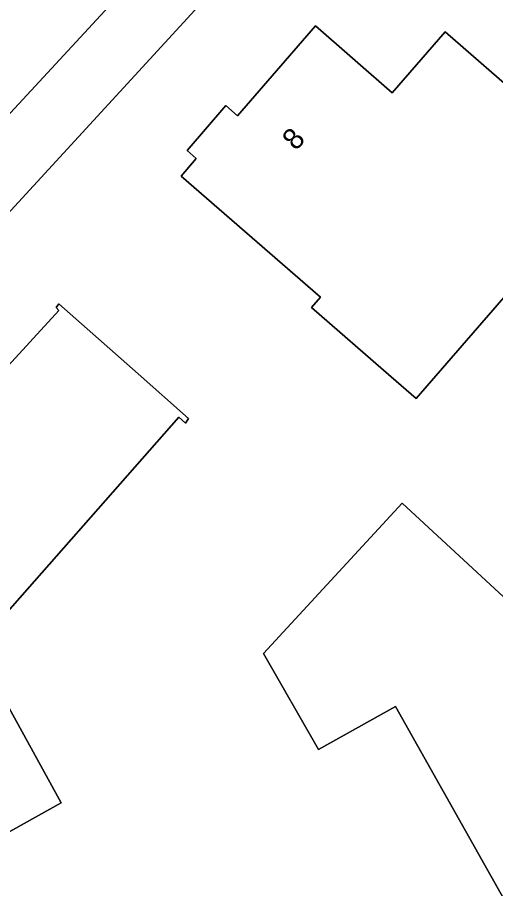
# Model space of a CAD drawing. Extents: x 160023 to 161302, y 384750 to 385707.
# Drawn here: x 160547.86 to 160570.51, y 385276.49 to 385317.72 of the extents above; entities that cross this region are included whole.
import ezdxf

# ---------------------------------------------------------------- set-up
doc = ezdxf.new("R2010")
doc.units = 0
for name, color, linetype in [('IMGEO_Erf', 7, 'Continuous'), ('IMGEO_Pand', 7, 'Continuous'), ('IMGEO_Pand_nummerreeks', 7, 'Continuous'), ('IMGEO_Rijbaan_lokaal_open', 7, 'Continuous'), ('IMGEO_Voetpad_open', 7, 'Continuous')]:
    doc.layers.add(name, color=color, linetype=linetype)

msp = doc.modelspace()

# ---------------------------------------------------------------- linework, layer by layer
at = {"layer": 'IMGEO_Erf'}
msp.add_lwpolyline([(160574.043, 385337.42), (160530.106, 385289.633), (160548.644, 385257.254), (160549.531, 385257.908), (160555.291, 385261.732), (160553.213, 385265.368), (160550.807, 385263.771), (160546.893, 385270.637), (160549.849, 385272.493), (160549.704, 385272.761), (160550.78, 385273.373), (160550.914, 385273.139), (160555.294, 385275.553), (160555.932, 385275.904), (160559.029, 385270.29), (160562.892, 385272.317), (160564.94, 385269.231), (160560.974, 385265.499), (160564.337, 385260.433), (160563.562, 385259.919), (160566.095, 385256.103), (160560.202, 385252.19), (160558.995, 385251.389), (160560.062, 385249.782)], dxfattribs=at)
for points in [[(160574.27, 385301.957), (160571.104, 385304.708), (160566.745, 385299.691), (160565.566, 385300.716), (160561.791, 385303.995), (160562.209, 385304.476), (160555.608, 385310.212), (160556.331, 385311.045), (160555.893, 385311.425), (160557.734, 385313.544), (160558.282, 385313.068), (160561.971, 385317.313), (160565.616, 385314.146), (160568.122, 385317.03), (160571.897, 385313.751), (160579.015, 385307.566), (160581.581, 385310.519), (160579.316, 385312.486), (160581.698, 385315.228), (160586.085, 385311.418), (160583.703, 385308.676), (160587.666, 385305.233), (160584.69, 385301.807), (160578.624, 385307.076)], [(160545.875, 385287.891), (160546.647, 385286.494), (160549.935, 385280.544), (160547.638, 385279.274), (160543.261, 385276.855), (160538.06, 385286.264), (160540.539, 385289.048), (160538.078, 385291.24), (160538.242, 385291.512), (160538.536, 385291.335), (160542.207, 385295.461), (160541.895, 385295.738), (160544.204, 385298.309), (160544.488, 385298.045), (160549.819, 385303.853), (160549.684, 385303.992), (160549.819, 385304.157), (160553.57, 385300.851), (160555.96, 385298.744), (160555.824, 385298.519), (160555.505, 385298.795)], [(160571.341, 385275.212), (160565.771, 385285.111), (160562.121, 385283.08), (160559.517, 385287.619), (160566.089, 385294.733), (160579.218, 385282.604)]]:
    msp.add_lwpolyline(points, close=True, dxfattribs=at)
at = {"layer": 'IMGEO_Pand'}
for points in [[(160579.015, 385307.566), (160571.897, 385313.751), (160568.122, 385317.03), (160565.616, 385314.146), (160561.971, 385317.313), (160558.282, 385313.068), (160557.734, 385313.544), (160555.893, 385311.425), (160556.331, 385311.045), (160555.608, 385310.212), (160562.209, 385304.476), (160561.791, 385303.995), (160565.566, 385300.716), (160566.745, 385299.691), (160571.104, 385304.708), (160574.27, 385301.957), (160578.624, 385307.076), (160584.69, 385301.807), (160587.666, 385305.233), (160583.703, 385308.676), (160586.085, 385311.418), (160581.698, 385315.228), (160579.316, 385312.486), (160581.581, 385310.519)], [(160555.505, 385298.795), (160555.824, 385298.519), (160555.96, 385298.744), (160553.57, 385300.851), (160549.819, 385304.157), (160549.684, 385303.992), (160549.819, 385303.853), (160544.488, 385298.045), (160544.204, 385298.309), (160541.895, 385295.738), (160542.207, 385295.461), (160538.536, 385291.335), (160538.242, 385291.512), (160538.078, 385291.24), (160540.539, 385289.048), (160538.06, 385286.264), (160543.261, 385276.855), (160547.638, 385279.274), (160549.935, 385280.544), (160546.647, 385286.494), (160545.875, 385287.891)], [(160579.218, 385282.604), (160566.089, 385294.733), (160559.517, 385287.619), (160562.121, 385283.08), (160565.771, 385285.111), (160571.341, 385275.212)]]:
    msp.add_lwpolyline(points, close=True, dxfattribs=at)
at = {"layer": 'IMGEO_Rijbaan_lokaal_open'}
msp.add_lwpolyline([(160546.933, 385312.577), (160553.94, 385320.146), (160548.821, 385324.838), (160539.191, 385314.315), (160525.127, 385299.052)], dxfattribs=at)
at = {"layer": 'IMGEO_Voetpad_open'}
msp.add_lwpolyline([(160549.531, 385257.908), (160548.644, 385257.254), (160530.106, 385289.633), (160574.043, 385337.42), (160575.101, 385338.587), (160577.45, 385341.176), (160574.598, 385342.503), (160572.85, 385340.582), (160564.349, 385331.617), (160564.718, 385331.281), (160559.464, 385325.489), (160559.095, 385325.825), (160555.75, 385322.137), (160554.106, 385320.325), (160553.94, 385320.146), (160546.933, 385312.577), (160547.299, 385312.237), (160544.665, 385309.392), (160544.299, 385309.732), (160529.43, 385293.697)], dxfattribs=at)

# ---------------------------------------------------------------- texts
at = {"layer": 'IMGEO_Pand_nummerreeks'}
msp.add_text('8', height=1, rotation=48.1374, dxfattribs=at).set_placement((160561.051, 385311.372))

doc.saveas('drawing.dxf')
